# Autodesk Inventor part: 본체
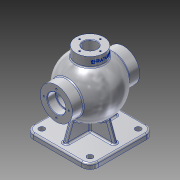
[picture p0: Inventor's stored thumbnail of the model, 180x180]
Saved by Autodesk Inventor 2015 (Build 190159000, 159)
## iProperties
Created: 2025-08
Part Number: 본체
Material: 알루미늄 6061
Document SubType Name: Modeling
Designer: USER
Density: 2.7 g/cm^3
Appearance: 알루미늄 - 평지
Mass: 1526.72 g
Surface Area: 1173.82 cm^2
Volume: 565.453 cm^3
Author: USER
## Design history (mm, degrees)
sketch "스케치1"
  geometry: L1 (-62.5, -62.5)-(62.5, -62.5); L2 (62.5, -62.5)-(62.5, 62.5); L3 (62.5, 62.5)-(-62.5, 62.5); L4 (-62.5, 62.5)-(-62.5, -62.5); L5 (-62.5, -62.5)-(62.5, 62.5); L6 (62.5, -62.5)-(-62.5, 62.5); 1 further point
  constraints: 12 end point, 2 midpoint, 2 parallel, 1 horizontal, 1 perpendicular
  dimensions: "d0" = 125 distance of L3.end L2.end; "d1" = 125 distance of L2.end L1.end
extrude "돌출1" new body sketch "스케치1" distance "d2" = 10; taper "d3" = 0 deg
fillet "모깎기1" dims "d4" = 16
sketch "스케치2"
  geometry: L1 (62.5, 10)-(62.5, 0) reference; L2 (62.5, 0)-(-62.5, 0) reference; L3 (-62.5, 0)-(-62.5, 10) reference; L4 (-62.5, 10)-(62.5, 10) reference; L5 (0, 0)-(0, 85); L6 (-65, 85)-(65, 85); L7 (-65, 85)-(-65, 116); L8 (-65, 116)-(-44.215, 116); L9 (65, 116)-(65, 85); L10 (65, 116)-(44.215, 116); A1 r 54 centre (0, 85) between (54, 85) and (-54, 85); A2 r 44 centre (0, 85) between (44, 85) and (-44, 85); 1 further point
  constraints: 12 end point, 6 point on circle, 6 point on line, 2 centre point, 2 coincident, 2 perpendicular, 2 vertical, 1 horizontal, 1 midpoint
  dimensions: "d5" = 85 distance of L5.end L5.start; "d6" = 108 diameter of A1; "d7" = 88 diameter of A2; "d8" = 130 distance of L6.start L6.end; "d9" = 31 distance of L6.start L7.end
revolve "회전1" sketch "스케치2" stored, may be unused: angle "d10" = 90 deg
node "작업 평면1"
sketch "스케치3"
  geometry: C1 r 27 at (0, 0); 1 further point
  constraints: 1 centre point, 1 coincident
  dimensions: "d12" = 54 diameter of C1
extrude "돌출2" join sketch "스케치3" stored distance "d13" = 10; taper "d14" = 0 deg
sketch "스케치5"
  geometry: L1 (46.5, -62.5)-(-46.5, -62.5) reference; L2 (-62.5, -46.5)-(-62.5, 46.5) reference; L3 (-46.5, 62.5)-(46.5, 62.5) reference; L4 (62.5, 46.5)-(62.5, -46.5) reference; L5 (-4, 50.5)-(4, 50.5); L6 (4, 50.5)-(4, -50.5); L7 (4, -50.5)-(-4, -50.5); L8 (-4, -50.5)-(-4, 50.5); L9 (-50.5, 4)-(50.5, 4); L10 (50.5, 4)-(50.5, -4); L11 (50.5, -4)-(-50.5, -4); L12 (-50.5, -4)-(-50.5, 4); A1 r 16 centre (46.5, -46.5) between (46.5, -62.5) and (62.5, -46.5) reference; A2 r 16 centre (-46.5, -46.5) between (-62.5, -46.5) and (-46.5, -62.5) reference; A3 r 16 centre (-46.5, 46.5) between (-46.5, 62.5) and (-62.5, 46.5) reference; A4 r 16 centre (46.5, 46.5) between (62.5, 46.5) and (46.5, 62.5) reference; 3 further points
  constraints: 16 end point, 4 parallel, 2 horizontal, 2 midpoint, 2 perpendicular, 1 horizontal alignment, 1 vertical alignment
  dimensions: "d19" = 8 distance of L6.end L7.end; "d20" = 12 distance between parallel lines of L4 L10; "d21" = 12 distance between parallel lines of L2 L12; "d22" = 12 distance between parallel lines of L3 L5; "d23" = 12 distance between parallel lines of L1 L7; "d24" = 8 distance of L9.end L10.end
extrude "돌출3" join sketch "스케치5" stored distance "d25" = 8; taper "d26" = 0 deg
feature "면 기울기1" dims angle "d27" = 20 deg
feature "면 기울기2" dims angle "d28" = 20 deg
feature "면 기울기3" dims angle "d29" = 20 deg
feature "면 기울기4" dims angle "d30" = 20 deg
hole "구멍1" diameter "d33" = 30; stored, may be unused: countersink angle "d37" = 90 deg, drill point angle "d39" = 0 deg; dims "d31" = 10, "d32" = 10, "d34" = 6, "d35" = 35, "d36" = 16, "d38" = 8
hole "구멍2" diameter "d42" = 35; stored, may be unused: countersink angle "d46" = 90 deg, drill point angle "d48" = 0 deg; dims "d40" = 10, "d41" = 10, "d43" = 6, "d44" = 35, "d45" = 16, "d47" = 16
chamfer "모따기2" distance "d52" = 1; stored, may be unused: second distance "d53" = 2, angle "d54" = 45 deg
sketch "스케치6"
  geometry: C1 r 13 at (0, 0); 1 further point
  constraints: 1 centre point, 1 coincident
  dimensions: "d55" = 26 diameter of C1
extrude "돌출4" cut sketch "스케치6" stored distance "d56" = 8; taper "d57" = 0 deg
chamfer "모따기3" distance "d58" = 1; stored, may be unused: second distance "d59" = 2, angle "d60" = 45 deg
sketch "스케치7"
  geometry: L1 (0, 0)-(0, 24); L2 (13, 42.036)-(-13, 42.036) reference; C1 r 18.5 at (0, 0) reference; C2 r 31 at (0, 0) reference; 1 further point
  constraints: 2 end point, 1 perpendicular
  dimensions: "d61" = 24 distance of L1.start L1.end
hole "구멍3" sketch "스케치7" at (0, 24) diameter "d62" = 3.242; stored, may be unused: countersink angle "d66" = 90 deg, drill point angle "d68" = 118 deg; dims "d63" = 12, "d64" = 35, "d65" = 16, "d67" = 15
fillet "모깎기2" dims "d72" = 0.6
sketch "스케치8"
  geometry: L1 (0, 0)-(0, 20); C1 r 14 at (0, 0) reference; C2 r 27 at (0, 0) reference; 1 further point
  constraints: 2 end point, 1 vertical
  dimensions: "d73" = 20 distance of L1.start L1.end
hole "구멍4" sketch "스케치8" at (0, 20) diameter "d74" = 3.242; stored, may be unused: countersink angle "d78" = 90 deg, drill point angle "d80" = 118 deg; dims "d75" = 8, "d76" = 35, "d77" = 16, "d79" = 11
fillet "모깎기3" dims "d84" = 3
fillet "모깎기4" dims "d85" = 3
fillet "모깎기5" dims "d86" = 3
fillet "모깎기6" dims "d87" = 3
fillet "모깎기7" dims "d88" = 3
fillet "모깎기8" dims "d89" = 3
fillet "모깎기9" dims "d90" = 3
sketch "스케치9"
  geometry: L1 (-46.5, 46.5)-(46.5, 46.5); L2 (46.5, 46.5)-(46.5, -46.5); L3 (46.5, -46.5)-(-46.5, -46.5); L4 (-46.5, -46.5)-(-46.5, 46.5); L5 (-46.5, 46.5)-(46.5, -46.5); L6 (46.5, 46.5)-(-46.5, -46.5); 1 further point
  constraints: 12 end point, 2 midpoint, 2 parallel, 1 horizontal, 1 perpendicular
  dimensions: "d91" = 93 distance of L2.end L3.end; "d92" = 93 distance of L1.end L2.end
hole "구멍5" sketch "스케치9" at (-46.5, -46.5) diameter "d93" = 11; stored, may be unused: countersink angle "d97" = 90 deg, drill point angle "d99" = 0 deg; dims "d94" = 8, "d95" = 35, "d96" = 16, "d98" = 11
sketch "스케치10"
  geometry: L1 (14, 150)-(-14, 150) reference; L2 (-50, 59.379)-(-49.026, 61) reference; L3 (-49.026, 61)-(-50, 62.621) reference; L4 (-50, 62.621)-(-65, 62.621) reference; L5 (-65, 62.621)-(-65, 66.5) reference; L6 (-65, 66.5)-(-64, 67.5) reference; L7 (-64, 67.5)-(-49.6, 67.5) reference; L8 (-49, 68.1)-(-49, 70) reference; L9 (-49, 70)-(-41.364, 70) reference; L10 (41.364, 70)-(49, 70) reference; L11 (49, 70)-(49, 68.1) reference; L12 (49.6, 67.5)-(64, 67.5) reference; L13 (64, 67.5)-(65, 66.5) reference; L14 (65, 66.5)-(65, 62.621) reference; L15 (65, 62.621)-(50, 62.621) reference; L16 (50, 62.621)-(49.026, 61) reference; L17 (49.026, 61)-(50, 59.379) reference; L18 (50, 59.379)-(65, 59.379) reference; L19 (65, 59.379)-(65, 54) reference; L20 (65, 54)-(45.749, 54) reference; L21 (38.041, 44.231)-(49.782, 11.974) reference; L22 (52.601, 10)-(59.5, 10) reference; L23 (62.5, 7)-(62.5, 0) reference; L24 (62.5, 0)-(-62.5, 0) reference; L25 (-62.5, 0)-(-62.5, 7) reference; L26 (-59.5, 10)-(-52.601, 10) reference; L27 (-49.782, 11.974)-(-38.041, 44.231) reference; L28 (-45.749, 54)-(-65, 54) reference; L29 (-65, 54)-(-65, 59.379) reference; L30 (-65, 59.379)-(-50, 59.379) reference; L31 (-14, 150)-(-13, 149) reference; L32 (-13, 149)-(-13, 127.036) reference; L33 (-41.364, 100)-(-49, 100) reference; L34 (-49, 100)-(-49, 101.9) reference; L35 (-49.6, 102.5)-(-64, 102.5) reference; L36 (-64, 102.5)-(-65, 103.5) reference; L37 (-65, 103.5)-(-65, 107.379) reference; L38 (-65, 107.379)-(-50, 107.379) reference; L39 (-50, 107.379)-(-49.026, 109) reference; L40 (-49.026, 109)-(-50, 110.621) reference; L41 (-50, 110.621)-(-65, 110.621) reference; L42 (-65, 110.621)-(-65, 116) reference; L43 (-65, 116)-(-45.749, 116) reference; L44 (-27, 133.466)-(-27, 150) reference; L45 (-27, 150)-(-21.621, 150) reference; L46 (-21.621, 150)-(-21.621, 139) reference; L47 (-21.621, 139)-(-20, 138.026) reference; L48 (-20, 138.026)-(-18.379, 139) reference; L49 (-18.379, 139)-(-18.379, 150) reference; L50 (-18.379, 150)-(-14, 150) reference; L51 (13, 149)-(14, 150) reference; L52 (14, 150)-(18.379, 150) reference; L53 (18.379, 150)-(18.379, 139) reference; L54 (18.379, 139)-(20, 138.026) reference; L55 (20, 138.026)-(21.621, 139) reference; L56 (21.621, 139)-(21.621, 150) reference; L57 (21.621, 150)-(27, 150) reference; L58 (27, 150)-(27, 133.466) reference; L59 (45.749, 116)-(65, 116) reference; L60 (65, 116)-(65, 110.621) reference; L61 (65, 110.621)-(50, 110.621) reference; L62 (50, 110.621)-(49.026, 109) reference; L63 (49.026, 109)-(50, 107.379) reference; L64 (50, 107.379)-(65, 107.379) reference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; A1 r 0.6 centre (-49.6, 68.1) between (-49.6, 67.5) and (-49, 68.1) reference; A2 r 44 centre (0, 85) between (-41.364, 70) and (41.364, 70) reference; A3 r 0.6 centre (49.6, 68.1) between (49, 68.1) and (49.6, 67.5) reference; A4 r 3 centre (45.749, 51) between (45.749, 54) and (43.341, 52.789) reference; A5 r 54 centre (0, 85) between (38.709, 47.349) and (43.341, 52.789) reference; A6 r 3 centre (40.86, 45.257) between (38.709, 47.349) and (38.041, 44.231) reference; A7 r 3 centre (52.601, 13) between (49.782, 11.974) and (52.601, 10) reference; A8 r 3 centre (59.5, 7) between (62.5, 7) and (59.5, 10) reference; A9 r 3 centre (-59.5, 7) between (-59.5, 10) and (-62.5, 7) reference; A10 r 3 centre (-52.601, 13) between (-52.601, 10) and (-49.782, 11.974) reference; A11 r 3 centre (-40.86, 45.257) between (-38.041, 44.231) and (-38.709, 47.349) reference; A12 r 54 centre (0, 85) between (-43.341, 52.789) and (-38.709, 47.349) reference; A13 r 3 centre (-45.749, 51) between (-43.341, 52.789) and (-45.749, 54) reference; A14 r 44 centre (0, 85) between (-13, 127.036) and (-41.364, 100) reference; A15 r 0.6 centre (-49.6, 101.9) between (-49, 101.9) and (-49.6, 102.5) reference; A16 r 3 centre (-45.749, 119) between (-45.749, 116) and (-43.341, 117.211) reference; A17 r 54 centre (0, 85) between (-28.421, 130.916) and (-43.341, 117.211) reference; A18 r 3 centre (-30, 133.466) between (-28.421, 130.916) and (-27, 133.466) reference; A19 r 3 centre (30, 133.466) between (27, 133.466) and (28.421, 130.916) reference; A20 r 54 centre (0, 85) between (43.341, 117.211) and (28.421, 130.916) reference; A21 r 3 centre (45.749, 119) between (43.341, 117.211) and (45.749, 116) reference; A22 r 0.6 centre (49.6, 101.9) between (49.6, 102.5) and (49, 101.9) reference; A23 r 44 centre (0, 85) between (41.364, 100) and (13, 127.036) reference; 2 further points
  constraints: 1 vertical alignment, 1 other
  dimensions: "d106" = 9 distance from line of L1 point (0, 141)
feature "엠보싱1" sketch "스케치10" dims "d5" = 85, "d6" = 108, "d7" = 88, "d8" = 130, "d9" = 31, "d107" = 0.5, "d108" = 0
node "솔리드1"
pattern_circular "원형 패턴1" dims angle "d70" = 360 deg
mirror "대칭1"
pattern_circular "원형 패턴2" dims angle "d82" = 360 deg
pattern_linear "직사각형 패턴1" dims "d102" = 93, "d105" = 93
node "절단 모서리 투영1"
node "절단 모서리 투영3"
node "절단 모서리 투영4"
node "절단 모서리 투영5"
node "절단 모서리 투영6"
